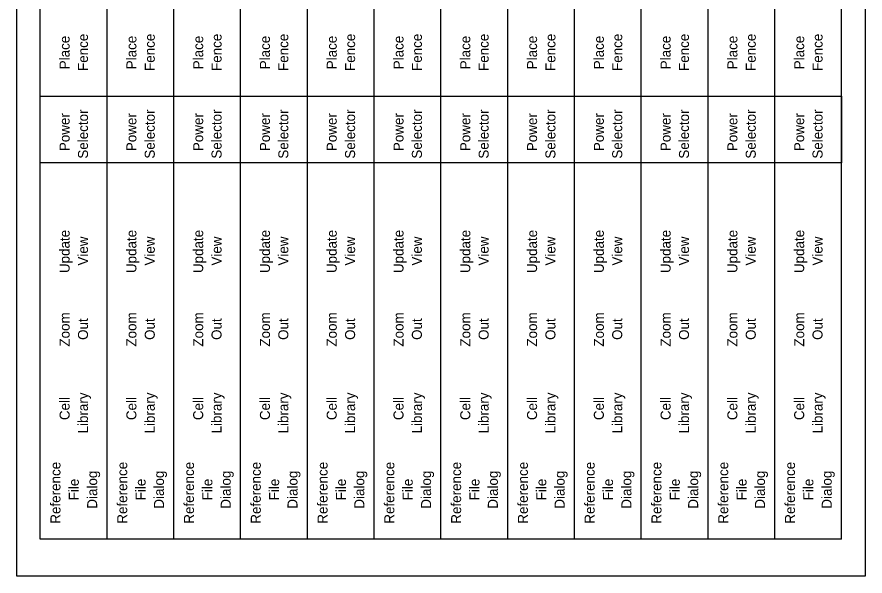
# Model space of a CAD drawing. Extents: x 605371.3 to 605398.1, y 420183.2 to 420214.1.
# Drawn here: x 605390.9472 to 605391.1504, y 420197.3447 to 420197.4785 of the extents above; entities that cross this region are included whole.
import ezdxf

# ---------------------------------------------------------------- set-up
doc = ezdxf.new("R2010")
doc.units = 0
for name, color, linetype in [('Hatch_Shade', 7, 'Continuous'), ('Level 60', 7, 'Continuous'), ('Notes', 7, 'Continuous')]:
    doc.layers.add(name, color=color, linetype=linetype)

msp = doc.modelspace()

# ---------------------------------------------------------------- linework, layer by layer
at = {"layer": 'Hatch_Shade'}
msp.add_lwpolyline([(605390.95278, 420197.4596), (605391.14478, 420197.4596), (605391.14478, 420197.4436), (605390.95278, 420197.4436)], close=True, dxfattribs=at)
at = {"layer": 'Level 60'}
msp.add_lwpolyline([(605391.15038, 420197.34467), (605390.94718, 420197.34467), (605390.94718, 420197.61237), (605391.15038, 420197.61237)], close=True, dxfattribs=at)
msp.add_lwpolyline([(605391.15038, 420197.34467), (605390.94718, 420197.34467), (605390.94718, 420197.61237), (605391.15038, 420197.61237)], close=True, dxfattribs=at)
at = {"layer": 'Notes'}
for p, q in [((605390.95278, 420197.35352), (605390.95278, 420197.60352)), ((605390.95278, 420197.35352), (605390.95278, 420197.60352)), ((605390.96878, 420197.35352), (605390.96878, 420197.60352)), ((605390.96878, 420197.35352), (605390.96878, 420197.60352)), ((605390.98478, 420197.35352), (605390.98478, 420197.60352)), ((605390.98478, 420197.35352), (605390.98478, 420197.60352)), ((605391.00078, 420197.35352), (605391.00078, 420197.60352)), ((605391.00078, 420197.35352), (605391.00078, 420197.60352)), ((605391.01678, 420197.35352), (605391.01678, 420197.60352)), ((605391.01678, 420197.35352), (605391.01678, 420197.60352)), ((605391.03278, 420197.35352), (605391.03278, 420197.60352)), ((605391.03278, 420197.35352), (605391.03278, 420197.60352)), ((605391.04878, 420197.35352), (605391.04878, 420197.60352)), ((605391.04878, 420197.35352), (605391.04878, 420197.60352)), ((605391.06478, 420197.35352), (605391.06478, 420197.60352)), ((605391.06478, 420197.35352), (605391.06478, 420197.60352)), ((605391.08078, 420197.35352), (605391.08078, 420197.60352)), ((605391.08078, 420197.35352), (605391.08078, 420197.60352)), ((605391.09678, 420197.35352), (605391.09678, 420197.60352)), ((605391.09678, 420197.35352), (605391.09678, 420197.60352)), ((605391.11278, 420197.35352), (605391.11278, 420197.60352)), ((605391.11278, 420197.35352), (605391.11278, 420197.60352)), ((605391.12878, 420197.35352), (605391.12878, 420197.60352)), ((605391.12878, 420197.35352), (605391.12878, 420197.60352)), ((605391.14478, 420197.35352), (605391.14478, 420197.60352)), ((605391.14478, 420197.35352), (605391.14478, 420197.60352)), ((605390.96878, 420197.35352), (605390.95278, 420197.35352)), ((605390.96878, 420197.35352), (605390.95278, 420197.35352)), ((605390.98478, 420197.35352), (605390.96878, 420197.35352)), ((605390.98478, 420197.35352), (605390.96878, 420197.35352)), ((605391.00078, 420197.35352), (605390.98478, 420197.35352)), ((605391.00078, 420197.35352), (605390.98478, 420197.35352)), ((605391.01678, 420197.35352), (605391.00078, 420197.35352)), ((605391.01678, 420197.35352), (605391.00078, 420197.35352)), ((605391.03278, 420197.35352), (605391.01678, 420197.35352)), ((605391.03278, 420197.35352), (605391.01678, 420197.35352)), ((605391.04878, 420197.35352), (605391.03278, 420197.35352)), ((605391.04878, 420197.35352), (605391.03278, 420197.35352)), ((605391.06478, 420197.35352), (605391.04878, 420197.35352)), ((605391.06478, 420197.35352), (605391.04878, 420197.35352)), ((605391.08078, 420197.35352), (605391.06478, 420197.35352)), ((605391.08078, 420197.35352), (605391.06478, 420197.35352)), ((605391.09678, 420197.35352), (605391.08078, 420197.35352)), ((605391.09678, 420197.35352), (605391.08078, 420197.35352)), ((605391.11278, 420197.35352), (605391.09678, 420197.35352)), ((605391.11278, 420197.35352), (605391.09678, 420197.35352)), ((605391.12878, 420197.35352), (605391.11278, 420197.35352)), ((605391.12878, 420197.35352), (605391.11278, 420197.35352)), ((605391.14478, 420197.35352), (605391.12878, 420197.35352)), ((605391.14478, 420197.35352), (605391.12878, 420197.35352))]:
    msp.add_line(p, q, dxfattribs=at)

# ---------------------------------------------------------------- texts
for s, p in [('Place', (605390.9598, 420197.466)), ('Place', (605390.9598, 420197.466)), ('Fence', (605390.9642, 420197.4656)), ('Fence', (605390.9642, 420197.4656)), ('Place', (605390.9758, 420197.466)), ('Place', (605390.9758, 420197.466)), ('Fence', (605390.9802, 420197.4656)), ('Fence', (605390.9802, 420197.4656)), ('Place', (605390.9918, 420197.466)), ('Place', (605390.9918, 420197.466)), ('Fence', (605390.9962, 420197.4656)), ('Fence', (605390.9962, 420197.4656)), ('Place', (605391.0078, 420197.466)), ('Place', (605391.0078, 420197.466)), ('Fence', (605391.0122, 420197.4656)), ('Fence', (605391.0122, 420197.4656)), ('Place', (605391.0238, 420197.466)), ('Place', (605391.0238, 420197.466)), ('Fence', (605391.0282, 420197.4656)), ('Fence', (605391.0282, 420197.4656)), ('Place', (605391.0398, 420197.466)), ('Place', (605391.0398, 420197.466)), ('Fence', (605391.0442, 420197.4656)), ('Fence', (605391.0442, 420197.4656)), ('Place', (605391.0558, 420197.466)), ('Place', (605391.0558, 420197.466)), ('Fence', (605391.0602, 420197.4656)), ('Fence', (605391.0602, 420197.4656)), ('Place', (605391.0718, 420197.466)), ('Place', (605391.0718, 420197.466)), ('Fence', (605391.0762, 420197.4656)), ('Fence', (605391.0762, 420197.4656)), ('Place', (605391.0878, 420197.466)), ('Place', (605391.0878, 420197.466)), ('Fence', (605391.0922, 420197.4656)), ('Fence', (605391.0922, 420197.4656)), ('Place', (605391.1038, 420197.466)), ('Place', (605391.1038, 420197.466)), ('Fence', (605391.1082, 420197.4656)), ('Fence', (605391.1082, 420197.4656)), ('Place', (605391.1198, 420197.466)), ('Place', (605391.1198, 420197.466)), ('Fence', (605391.1242, 420197.4656)), ('Fence', (605391.1242, 420197.4656)), ('Place', (605391.1358, 420197.466)), ('Place', (605391.1358, 420197.466)), ('Fence', (605391.1402, 420197.4656)), ('Fence', (605391.1402, 420197.4656)), ('Power', (605390.9598, 420197.4464)), ('Selector', (605390.9642, 420197.4446)), ('Power', (605390.9758, 420197.4464)), ('Selector', (605390.9802, 420197.4446)), ('Power', (605390.9918, 420197.4464)), ('Selector', (605390.9962, 420197.4446)), ('Power', (605391.0078, 420197.4464)), ('Selector', (605391.0122, 420197.4446)), ('Power', (605391.0238, 420197.4464)), ('Selector', (605391.0282, 420197.4446)), ('Power', (605391.0398, 420197.4464)), ('Selector', (605391.0442, 420197.4446)), ('Power', (605391.0558, 420197.4464)), ('Selector', (605391.0602, 420197.4446)), ('Power', (605391.0718, 420197.4464)), ('Selector', (605391.0762, 420197.4446)), ('Power', (605391.0878, 420197.4464)), ('Selector', (605391.0922, 420197.4446)), ('Power', (605391.1038, 420197.4464)), ('Selector', (605391.1082, 420197.4446)), ('Power', (605391.1198, 420197.4464)), ('Selector', (605391.1242, 420197.4446)), ('Power', (605391.1358, 420197.4464)), ('Selector', (605391.1402, 420197.4446)), ('Update', (605390.9598, 420197.4172)), ('Update', (605390.9598, 420197.4172)), ('Update', (605390.9758, 420197.4172)), ('Update', (605390.9758, 420197.4172)), ('Update', (605390.9918, 420197.4172)), ('Update', (605390.9918, 420197.4172)), ('Update', (605391.0078, 420197.4172)), ('Update', (605391.0078, 420197.4172)), ('Update', (605391.0238, 420197.4172)), ('Update', (605391.0238, 420197.4172)), ('Update', (605391.0398, 420197.4172)), ('Update', (605391.0398, 420197.4172)), ('Update', (605391.0558, 420197.4172)), ('Update', (605391.0558, 420197.4172)), ('Update', (605391.0718, 420197.4172)), ('Update', (605391.0718, 420197.4172)), ('Update', (605391.0878, 420197.4172)), ('Update', (605391.0878, 420197.4172)), ('Update', (605391.1038, 420197.4172)), ('Update', (605391.1038, 420197.4172)), ('Update', (605391.1198, 420197.4172)), ('Update', (605391.1198, 420197.4172)), ('Update', (605391.1358, 420197.4172)), ('Update', (605391.1358, 420197.4172)), ('View', (605390.9642, 420197.419)), ('View', (605390.9642, 420197.419)), ('View', (605390.9802, 420197.419)), ('View', (605390.9802, 420197.419)), ('View', (605390.9962, 420197.419)), ('View', (605390.9962, 420197.419)), ('View', (605391.0122, 420197.419)), ('View', (605391.0122, 420197.419)), ('View', (605391.0282, 420197.419)), ('View', (605391.0282, 420197.419)), ('View', (605391.0442, 420197.419)), ('View', (605391.0442, 420197.419)), ('View', (605391.0602, 420197.419)), ('View', (605391.0602, 420197.419)), ('View', (605391.0762, 420197.419)), ('View', (605391.0762, 420197.419)), ('View', (605391.0922, 420197.419)), ('View', (605391.0922, 420197.419)), ('View', (605391.1082, 420197.419)), ('View', (605391.1082, 420197.419)), ('View', (605391.1242, 420197.419)), ('View', (605391.1242, 420197.419)), ('View', (605391.1402, 420197.419)), ('View', (605391.1402, 420197.419)), ('Zoom', (605390.9598, 420197.3996)), ('Zoom', (605390.9598, 420197.3996)), ('Out', (605390.9642, 420197.4012)), ('Out', (605390.9642, 420197.4012)), ('Zoom', (605390.9758, 420197.3996)), ('Zoom', (605390.9758, 420197.3996)), ('Out', (605390.9802, 420197.4012)), ('Out', (605390.9802, 420197.4012)), ('Zoom', (605390.9918, 420197.3996)), ('Zoom', (605390.9918, 420197.3996)), ('Out', (605390.9962, 420197.4012)), ('Out', (605390.9962, 420197.4012)), ('Zoom', (605391.0078, 420197.3996)), ('Zoom', (605391.0078, 420197.3996)), ('Out', (605391.0122, 420197.4012)), ('Out', (605391.0122, 420197.4012)), ('Zoom', (605391.0238, 420197.3996)), ('Zoom', (605391.0238, 420197.3996)), ('Out', (605391.0282, 420197.4012)), ('Out', (605391.0282, 420197.4012)), ('Zoom', (605391.0398, 420197.3996)), ('Zoom', (605391.0398, 420197.3996)), ('Out', (605391.0442, 420197.4012)), ('Out', (605391.0442, 420197.4012)), ('Zoom', (605391.0558, 420197.3996)), ('Zoom', (605391.0558, 420197.3996)), ('Out', (605391.0602, 420197.4012)), ('Out', (605391.0602, 420197.4012)), ('Zoom', (605391.0718, 420197.3996)), ('Zoom', (605391.0718, 420197.3996)), ('Out', (605391.0762, 420197.4012)), ('Out', (605391.0762, 420197.4012)), ('Zoom', (605391.0878, 420197.3996)), ('Zoom', (605391.0878, 420197.3996)), ('Out', (605391.0922, 420197.4012)), ('Out', (605391.0922, 420197.4012)), ('Zoom', (605391.1038, 420197.3996)), ('Zoom', (605391.1038, 420197.3996)), ('Out', (605391.1082, 420197.4012)), ('Out', (605391.1082, 420197.4012)), ('Zoom', (605391.1198, 420197.3996)), ('Zoom', (605391.1198, 420197.3996)), ('Out', (605391.1242, 420197.4012)), ('Out', (605391.1242, 420197.4012)), ('Zoom', (605391.1358, 420197.3996)), ('Zoom', (605391.1358, 420197.3996)), ('Out', (605391.1402, 420197.4012)), ('Out', (605391.1402, 420197.4012)), ('Library', (605390.9642, 420197.3788)), ('Library', (605390.9642, 420197.3788)), ('Library', (605390.9802, 420197.3788)), ('Library', (605390.9802, 420197.3788)), ('Library', (605390.9962, 420197.3788)), ('Library', (605390.9962, 420197.3788)), ('Library', (605391.0122, 420197.3788)), ('Library', (605391.0122, 420197.3788)), ('Library', (605391.0282, 420197.3788)), ('Library', (605391.0282, 420197.3788)), ('Library', (605391.0442, 420197.3788)), ('Library', (605391.0442, 420197.3788)), ('Library', (605391.0602, 420197.3788)), ('Library', (605391.0602, 420197.3788)), ('Library', (605391.0762, 420197.3788)), ('Library', (605391.0762, 420197.3788)), ('Library', (605391.0922, 420197.3788)), ('Library', (605391.0922, 420197.3788)), ('Library', (605391.1082, 420197.3788)), ('Library', (605391.1082, 420197.3788)), ('Library', (605391.1242, 420197.3788)), ('Library', (605391.1242, 420197.3788)), ('Library', (605391.1402, 420197.3788)), ('Library', (605391.1402, 420197.3788)), ('Cell', (605390.9598, 420197.382)), ('Cell', (605390.9598, 420197.382)), ('Cell', (605390.9758, 420197.382)), ('Cell', (605390.9758, 420197.382)), ('Cell', (605390.9918, 420197.382)), ('Cell', (605390.9918, 420197.382)), ('Cell', (605391.0078, 420197.382)), ('Cell', (605391.0078, 420197.382)), ('Cell', (605391.0238, 420197.382)), ('Cell', (605391.0238, 420197.382)), ('Cell', (605391.0398, 420197.382)), ('Cell', (605391.0398, 420197.382)), ('Cell', (605391.0558, 420197.382)), ('Cell', (605391.0558, 420197.382)), ('Cell', (605391.0718, 420197.382)), ('Cell', (605391.0718, 420197.382)), ('Cell', (605391.0878, 420197.382)), ('Cell', (605391.0878, 420197.382)), ('Cell', (605391.1038, 420197.382)), ('Cell', (605391.1038, 420197.382)), ('Cell', (605391.1198, 420197.382)), ('Cell', (605391.1198, 420197.382)), ('Cell', (605391.1358, 420197.382)), ('Cell', (605391.1358, 420197.382)), ('Reference', (605390.9576, 420197.3572)), ('Reference', (605390.9576, 420197.3572)), ('Reference', (605390.9736, 420197.3572)), ('Reference', (605390.9736, 420197.3572)), ('Reference', (605390.9896, 420197.3572)), ('Reference', (605390.9896, 420197.3572)), ('Reference', (605391.0056, 420197.3572)), ('Reference', (605391.0056, 420197.3572)), ('Reference', (605391.0216, 420197.3572)), ('Reference', (605391.0216, 420197.3572)), ('Reference', (605391.0376, 420197.3572)), ('Reference', (605391.0376, 420197.3572)), ('Reference', (605391.0536, 420197.3572)), ('Reference', (605391.0536, 420197.3572)), ('Reference', (605391.0696, 420197.3572)), ('Reference', (605391.0696, 420197.3572)), ('Reference', (605391.0856, 420197.3572)), ('Reference', (605391.0856, 420197.3572)), ('Reference', (605391.1016, 420197.3572)), ('Reference', (605391.1016, 420197.3572)), ('Reference', (605391.1176, 420197.3572)), ('Reference', (605391.1176, 420197.3572)), ('Reference', (605391.1336, 420197.3572)), ('Reference', (605391.1336, 420197.3572)), ('Dialog', (605390.9664, 420197.3608)), ('Dialog', (605390.9664, 420197.3608)), ('Dialog', (605390.9824, 420197.3608)), ('Dialog', (605390.9824, 420197.3608)), ('Dialog', (605390.9984, 420197.3608)), ('Dialog', (605390.9984, 420197.3608)), ('Dialog', (605391.0144, 420197.3608)), ('Dialog', (605391.0144, 420197.3608)), ('Dialog', (605391.0304, 420197.3608)), ('Dialog', (605391.0304, 420197.3608)), ('Dialog', (605391.0464, 420197.3608)), ('Dialog', (605391.0464, 420197.3608)), ('Dialog', (605391.0624, 420197.3608)), ('Dialog', (605391.0624, 420197.3608)), ('Dialog', (605391.0784, 420197.3608)), ('Dialog', (605391.0784, 420197.3608)), ('Dialog', (605391.0944, 420197.3608)), ('Dialog', (605391.0944, 420197.3608)), ('Dialog', (605391.1104, 420197.3608)), ('Dialog', (605391.1104, 420197.3608)), ('Dialog', (605391.1264, 420197.3608)), ('Dialog', (605391.1264, 420197.3608)), ('Dialog', (605391.1424, 420197.3608)), ('Dialog', (605391.1424, 420197.3608)), ('File', (605390.962, 420197.3628)), ('File', (605390.962, 420197.3628)), ('File', (605390.978, 420197.3628)), ('File', (605390.978, 420197.3628)), ('File', (605390.994, 420197.3628)), ('File', (605390.994, 420197.3628)), ('File', (605391.01, 420197.3628)), ('File', (605391.01, 420197.3628)), ('File', (605391.026, 420197.3628)), ('File', (605391.026, 420197.3628)), ('File', (605391.042, 420197.3628)), ('File', (605391.042, 420197.3628)), ('File', (605391.058, 420197.3628)), ('File', (605391.058, 420197.3628)), ('File', (605391.074, 420197.3628)), ('File', (605391.074, 420197.3628)), ('File', (605391.09, 420197.3628)), ('File', (605391.09, 420197.3628)), ('File', (605391.106, 420197.3628)), ('File', (605391.106, 420197.3628)), ('File', (605391.122, 420197.3628)), ('File', (605391.122, 420197.3628)), ('File', (605391.138, 420197.3628)), ('File', (605391.138, 420197.3628))]:
    msp.add_text(s, height=0.0024, rotation=90, dxfattribs=at).set_placement(p)

doc.saveas('drawing.dxf')
